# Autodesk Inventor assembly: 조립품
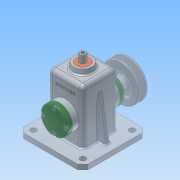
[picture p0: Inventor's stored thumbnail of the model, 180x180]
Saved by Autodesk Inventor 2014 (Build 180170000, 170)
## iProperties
Created: 2016-02
Part Number: 조립품
Document SubType Name: Assembly
Designer: net
Mass: 1852.44 g
Surface Area: 1674.59 cm^2
Volume: 492.92 cm^3
Density: 3.7581 g/cm^3
Author: net
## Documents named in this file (15)
- C:\Users\net\Desktop\460211V1018\조립품.iam
- C:\Users\net\Desktop\460211V1018\본체.ipt
- C:\Users\net\Desktop\460211V1018\뒤커버.ipt
- C:\Users\net\Desktop\460211V1018\베어링 12 x 32 x 10.ipt
- C:\Users\net\Desktop\460211V1018\볼트 M4 x 12.ipt
- C:\Users\net\Desktop\460211V1018\앞커버.ipt
- C:\Users\net\Desktop\460211V1018\오일실 12 25 7.ipt
- C:\Users\net\Desktop\460211V1018\편심축.ipt
- C:\Users\net\Desktop\460211V1018\키 4 x 4 x 10.ipt
- C:\Users\net\Desktop\460211V1018\V벨트풀리.ipt
- C:\Users\net\Desktop\460211V1018\링크.ipt
- C:\Users\net\Desktop\460211V1018\슬라이드.ipt
- C:\Users\net\Desktop\460211V1018\핀 5 x 18.ipt
- C:\Users\net\Desktop\460211V1018\멈춤나사 M3x8.ipt
- C:\Users\net\Desktop\460211V1018\부시.ipt
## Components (10 placed, 3 different names)
1. ISO 4762 M4 x 12:1
2. ISO 4762 M4 x 12:2
3. ISO 4762 M4 x 12:3
4. ISO 4762 M4 x 12:4
5. ISO 4762 M4 x 12:5
6. ISO 4762 M4 x 12:6
7. ISO 4762 M4 x 12:7
8. ISO 4762 M4 x 12:8
9. V벨트풀리:1 — 각도:2
10. 핀 5 x 18:1
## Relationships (1: Angle 1)
- 각도:2 [Angle]: V벨트풀리:1
